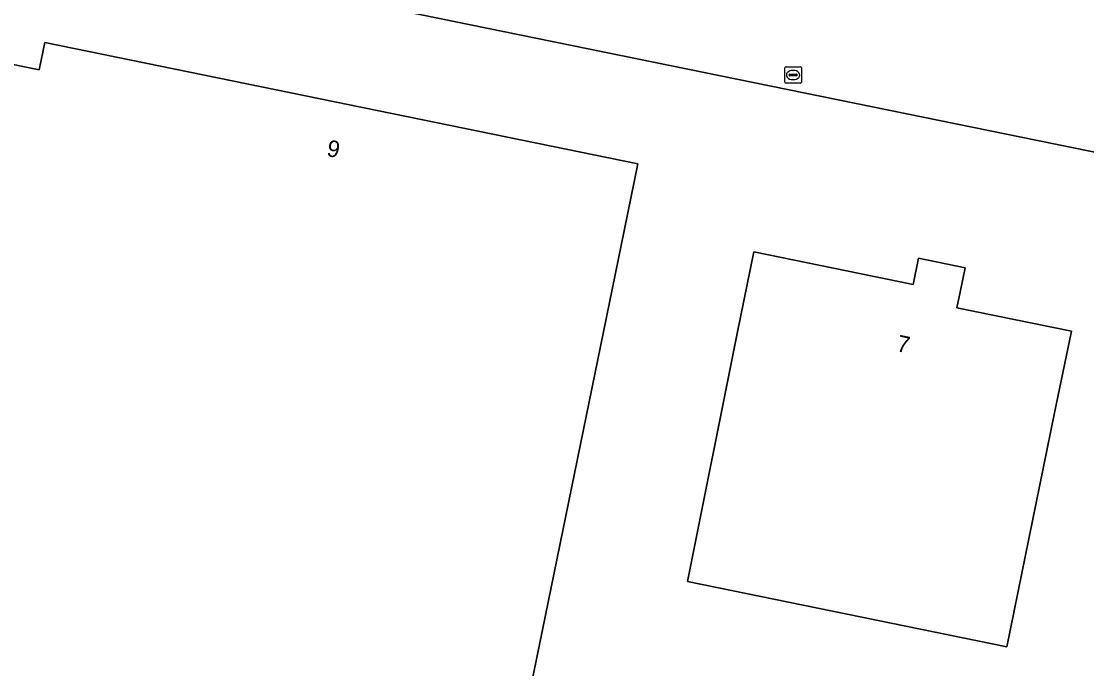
# Model space of a CAD drawing. Extents: x 157692 to 159674, y 381452 to 383291.
# Drawn here: x 158645.4 to 158709.4, y 382263.8 to 382302.7 of the extents above; entities that cross this region are included whole.
import ezdxf

# ---------------------------------------------------------------- set-up
doc = ezdxf.new("R2010")
doc.units = 0
for name, color, linetype in [('IMGEO_Brandkraan', 7, 'Continuous'), ('IMGEO_Erf', 7, 'Continuous'), ('IMGEO_Pand', 7, 'Continuous'), ('IMGEO_Pand_nummerreeks', 7, 'Continuous'), ('IMGEO_Voetpad_open', 7, 'Continuous')]:
    doc.layers.add(name, color=color, linetype=linetype)

msp = doc.modelspace()

# ---------------------------------------------------------------- linework, layer by layer
at = {"layer": 'IMGEO_Brandkraan'}
for p, q in [((158691.293, 382299.089), (158691.293, 382299.941)), ((158691.368, 382300.015), (158692.22, 382300.015)), ((158691.552, 382299.509), (158691.552, 382299.521)), ((158691.99, 382299.472), (158691.592, 382299.472)), ((158691.595, 382299.558), (158691.993, 382299.558)), ((158691.781, 382299.795), (158691.806, 382299.795)), ((158692.036, 382299.521), (158692.036, 382299.509)), ((158692.294, 382299.941), (158692.294, 382299.089)), ((158692.22, 382299.015), (158691.368, 382299.015)), ((158691.804, 382299.235), (158691.779, 382299.235))]:
    msp.add_line(p, q, dxfattribs=at)
for points in [[(158691.293, 382299.089), (158691.293, 382299.941)], [(158691.368, 382300.015), (158692.22, 382300.015)], [(158692.294, 382299.941), (158692.294, 382299.089)], [(158692.22, 382299.015), (158691.368, 382299.015)]]:
    msp.add_lwpolyline(points, dxfattribs=at)
for centre, radius, start, end in [((158691.37, 382299.939), 0.0765, 91.55205, 178.44795), ((158691.37, 382299.939), 0.0765, 91.55205, 178.44795), ((158691.592, 382299.518), 0.0403, 85.87752, 175.75265), ((158691.589, 382299.508), 0.0366, 178.93798, 274.71019), ((158691.993, 382299.515), 0.043, 264.86636, 352.45326), ((158691.997, 382299.52), 0.0386, 1.73085, 96.63898), ((158692.218, 382299.939), 0.0765, 1.55205, 88.44795), ((158692.218, 382299.939), 0.0765, 1.55205, 88.44795), ((158691.37, 382299.091), 0.0765, 181.55205, 268.44795), ((158691.37, 382299.091), 0.0765, 181.55205, 268.44795), ((158692.218, 382299.091), 0.0765, 271.55205, 358.44795), ((158692.218, 382299.091), 0.0765, 271.55205, 358.44795)]:
    msp.add_arc(centre, radius, start, end, dxfattribs=at)
for centre, major_axis, ratio, start_param, end_param in [((158691.78, 382299.515), (-0.387, 0.002), 0.722429, 4.712389, 7.853982), ((158691.805, 382299.515), (-0.39, 0.002), 0.717154, 1.570796, 4.712389)]:
    msp.add_ellipse(centre, major_axis=major_axis, ratio=ratio, start_param=start_param, end_param=end_param, dxfattribs=at)
at = {"layer": 'IMGEO_Erf'}
for points in [[(158774.915, 382281.626), (158583.923, 382320.599), (158578.836, 382321.712), (158578.49, 382320.049), (158577.977, 382317.433), (158573.17, 382294.226), (158571.648, 382286.878), (158568.676, 382272.426), (158569.594, 382272.252), (158568.934, 382269.03), (158568.022, 382269.232), (158563.842, 382248.283), (158559.221, 382225.883), (158556.642, 382213.448), (158553.461, 382197.47)], [(158579.611, 382287.573), (158581.414, 382287.202), (158582.889, 382294.403), (158586.862, 382313.802), (158629.037, 382305.165), (158628.692, 382303.476), (158636.008, 382301.978), (158646.495, 382299.831), (158646.831, 382301.468), (158682.461, 382294.172), (158681.458, 382289.274), (158674.443, 382255.016), (158638.933, 382262.288), (158635.885, 382247.407), (158625.252, 382249.584), (158619.878, 382250.685), (158600.86, 382254.58), (158601.058, 382255.546), (158598.989, 382255.97), (158598.787, 382254.979), (158586.303, 382257.536), (158584.749, 382250), (158581.669, 382235.069), (158570.413, 382237.369)]]:
    msp.add_lwpolyline(points, dxfattribs=at)
msp.add_lwpolyline([(158688.441, 382283.992), (158689.444, 382288.89), (158699.002, 382286.933), (158699.323, 382288.5), (158702.127, 382287.926), (158701.826, 382286.457), (158701.636, 382285.527), (158708.513, 382284.118), (158707.51, 382279.22), (158704.629, 382265.152), (158685.442, 382269.081)], close=True, dxfattribs=at)
at = {"layer": 'IMGEO_Pand'}
for points in [[(158636.008, 382301.978), (158625.252, 382249.584), (158635.885, 382247.407), (158638.933, 382262.288), (158674.443, 382255.016), (158681.458, 382289.274), (158682.461, 382294.172), (158646.831, 382301.468), (158646.495, 382299.831)], [(158701.826, 382286.457), (158702.127, 382287.926), (158699.323, 382288.5), (158699.002, 382286.933), (158689.444, 382288.89), (158688.441, 382283.992), (158685.442, 382269.081), (158704.629, 382265.152), (158707.51, 382279.22), (158708.513, 382284.118), (158701.636, 382285.527)]]:
    msp.add_lwpolyline(points, close=True, dxfattribs=at)
at = {"layer": 'IMGEO_Voetpad_open'}
msp.add_lwpolyline([(158585.636, 382328.823), (158583.923, 382320.599), (158774.915, 382281.626), (158775.174, 382281.573), (158776.28, 382289.179), (158776.115, 382289.213), (158776.367, 382290.437)], dxfattribs=at)

# ---------------------------------------------------------------- texts
at = {"layer": 'IMGEO_Pand_nummerreeks'}
for s, rotation, p in [('9', 348.42745, (158663.718, 382294.662)), ('7', 348.42115, (158697.965, 382282.931))]:
    msp.add_text(s, height=1, rotation=rotation, dxfattribs=at).set_placement(p)

doc.saveas('drawing.dxf')
